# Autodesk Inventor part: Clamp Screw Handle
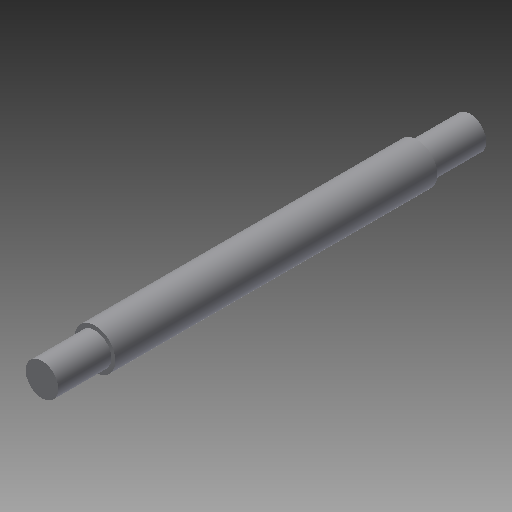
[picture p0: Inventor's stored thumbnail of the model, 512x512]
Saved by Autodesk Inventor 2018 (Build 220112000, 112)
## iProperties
Shininess: 77.0
Length Units: 11269
Angle Units: 11279
Time Units: 11290
Mass Units: 11283
Length Display Precision: 3
Angle Display Precision: 2
Compacted: True
Created: 2002-02
Part Number: Clamp Screw Handle
Document SubType Name: Modeling
Designer: ***
Density: 1 g/cm^3
Material: Generic
Appearance: Default
Density: 0.0
Volumn: 0.0
Area: 0.0
PropertySet Name: Model Information
Control State: 0
Master: False
Checked Out: False
Author: ***
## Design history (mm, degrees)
sketch "Sketch1"
  geometry: L1 (0, 105)-(4, 105); L2 (4, 105)-(4, 92); L3 (4, 92)-(5, 92); L4 (5, 92)-(5, 13); L5 (5, 13)-(4, 13); L6 (4, 13)-(4, 0); L7 (4, 0)-(0, 0); L8 (0, 0)-(0, 105)
  constraints: 16 end point, 5 parallel, 2 equal length, 1 collinear, 1 horizontal, 1 perpendicular
  dimensions: "d0" = 10 diameter of L4 L8; "d1" = 8 diameter of L2 L8; "d2" = 13 distance of L1.end L2.end; "d3" = 79 distance of L3.end L4.end
revolve "Revolution1" sketch "Sketch1" stored, may be unused: angle "d4" = 90 deg
body "Solid1"
